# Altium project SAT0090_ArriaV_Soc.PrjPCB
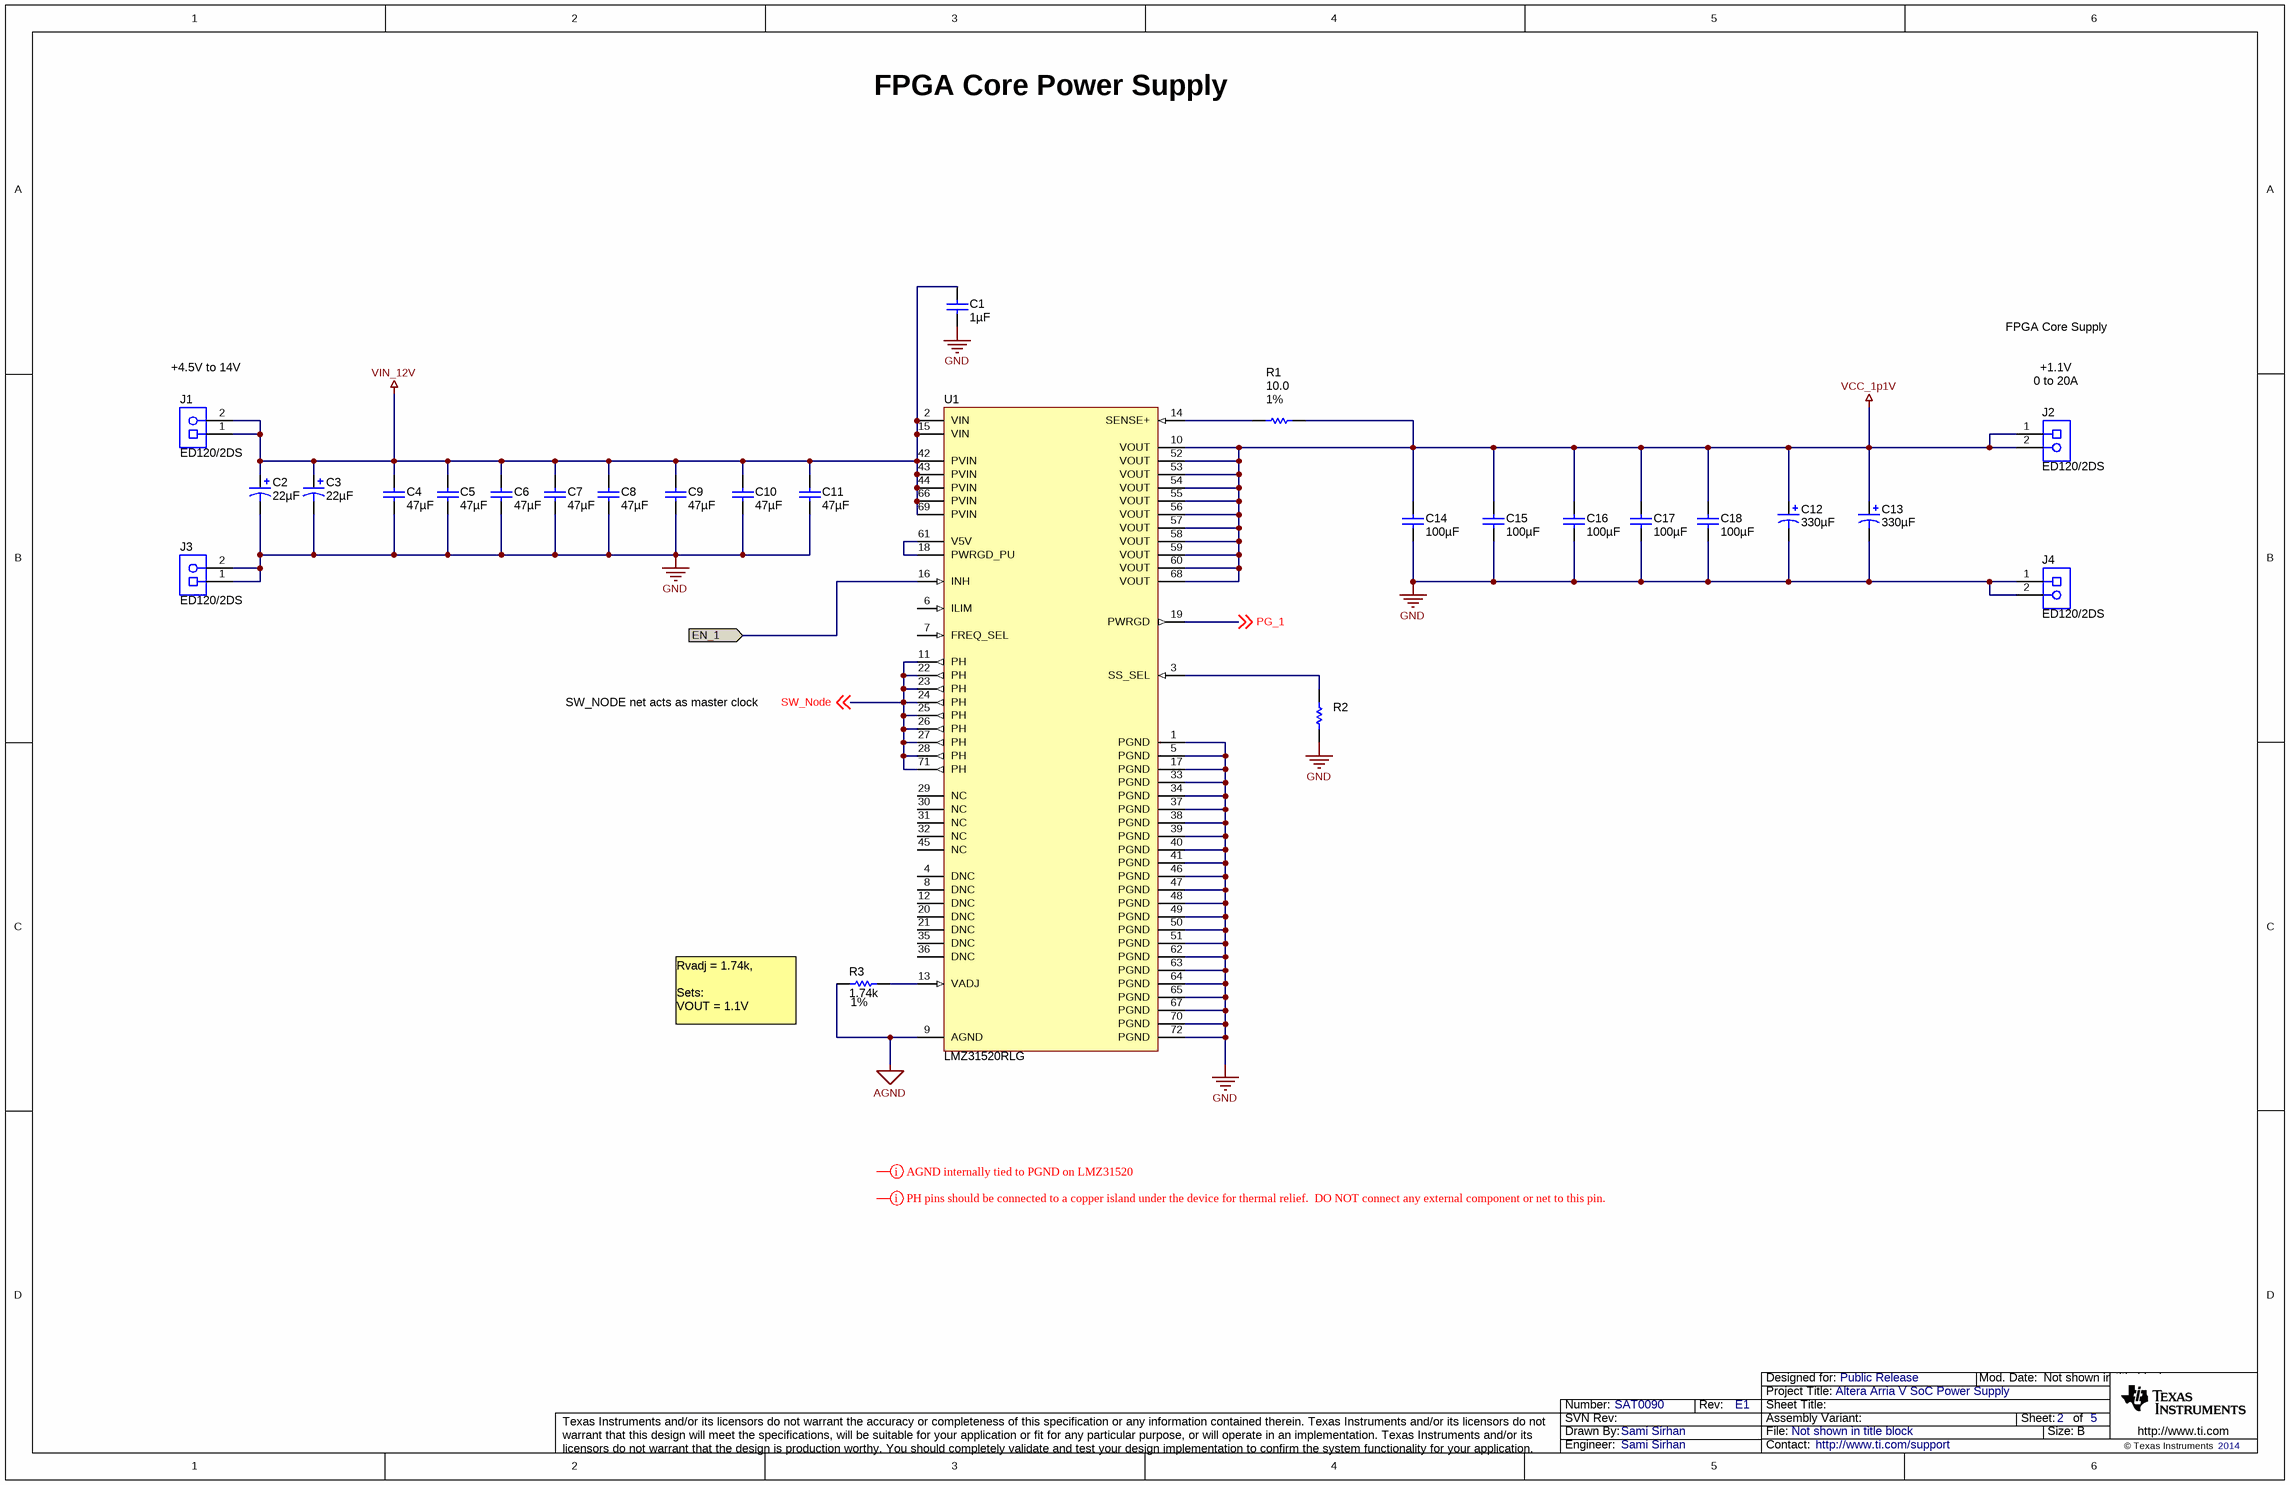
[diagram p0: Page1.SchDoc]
CopyrightYear: 2014; PCB_Layout: Sami Sirhan; PCB_Rev: E1; PRJ_Customer: Public Release; PRJ_Engineer: Sami Sirhan; PRJ_Number: SAT0090; PRJ_Title: Altera Arria V SoC Power Supply; SCH_Rev: E1; TechSupport: http://www.ti.com/support
5 sheets, 142 parts. Net scope: flat (ports and power ports of the same name join across sheets).
Sheets:
  Page1.SchDoc
  Page2.SchDoc
  Page3.SchDoc
  Page4.SchDoc
  Cover Sheet_ANSI-B.SchDoc

## Sheet Page1.SchDoc
size 431 x 279 mm; Date: Not shown in title block; ApprovedBy: Not shown in title block; CheckedBy: Not shown in title block; Author: Not shown in title block; CompanyName: Not shown in title block; DrawnBy: Sami Sirhan; Engineer: Not shown in title block; Organization: Not shown in title block; Address1: Not shown in title block; Address2: Not shown in title block; Address3: Not shown in title block; Address4: Not shown in title block; DocumentNumber: 2; Revision: Use project parameter SCH_Rev; SheetNumber: 2; SheetTotal: 5; PageSetup: Record=PageOptions|CenterHorizontal=True|CenterVertical=True|PrintScale=1.00|XCorrection=1.00|YCorrection=1.00|PrintKind=0|BorderSize=5000000|LeftOffset=0|BottomOffset=0|Orientation=2|PaperLength=1000|PaperWidth=1000|Scale=100|PaperSource=15|PrintQuality=600|MediaType=1|DitherType=10|PaperKind=Letter|PrintScaleMode=1

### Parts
(Parts that share a designator on the sheet are numbered #1, #2 ... from top to bottom, then left to right.)
C1#1  ValueDisplayed: 1µF  [0603]  (hidden comment: GRM188R61E105KA12D)
C2  ValueDisplayed: 22µF  [SM_RADIAL_C]  (hidden comment: EEE-FC1C220R)
C3  ValueDisplayed: 22µF  [SM_RADIAL_C]  (hidden comment: EEE-FC1C220R)
C4  ValueDisplayed: 47µF  [1210]  (hidden comment: GRM32ER61C476KE15L)
C5  ValueDisplayed: 47µF  [1210]  (hidden comment: GRM32ER61C476KE15L)
C6  ValueDisplayed: 47µF  [1210]  (hidden comment: GRM32ER61C476KE15L)
C7  ValueDisplayed: 47µF  [1210]  (hidden comment: GRM32ER61C476KE15L)
C8  ValueDisplayed: 47µF  [1210]  (hidden comment: GRM32ER61C476KE15L)
C9  ValueDisplayed: 47µF  [1210]  (hidden comment: GRM32ER61C476KE15L)
C10  ValueDisplayed: 47µF  [1210]  (hidden comment: GRM32ER61C476KE15L)
C11  ValueDisplayed: 47µF  [1210]  (hidden comment: GRM32ER61C476KE15L)
C12  ValueDisplayed: 330µF  [CAPAE_SP-Cap_Standard]  (hidden comment: EEF-SX0D331XE)
C13  ValueDisplayed: 330µF  [CAPAE_SP-Cap_Standard]  (hidden comment: EEF-SX0D331XE)
C14  ValueDisplayed: 100µF  [1210]  (hidden comment: GRM32ER60J107ME20L)
C15  ValueDisplayed: 100µF  [1210]  (hidden comment: GRM32ER60J107ME20L)
C16  ValueDisplayed: 100µF  [1210]  (hidden comment: GRM32ER60J107ME20L)
C17  ValueDisplayed: 100µF  [1210]  (hidden comment: GRM32ER60J107ME20L)
C18  ValueDisplayed: 100µF  [1210]  (hidden comment: GRM32ER60J107ME20L)
J1  ED120/2DS  [CONN_ED120-2DS]
J2  ED120/2DS  [CONN_ED120-2DS]
J3  ED120/2DS  [CONN_ED120-2DS]
J4  ED120/2DS  [CONN_ED120-2DS]
R1  value 10.0  Value1: 1%  [0603]  (hidden comment: CRCW060310R0FKEA)
R2  CRCW06030000Z0EA  [0603]  (value not drawn)
R3  value 1.74k  Value1: 1%  [0603]  (hidden comment: CRCW06031K74FKEA)
U1  LMZ31520RLG  [RLG0072A]

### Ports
EN_1 (in)

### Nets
AGND: R3.2 U1.9(AGND)
GND: C1#1.2 C2.2(-) C3.2(-) C4.2 C5.2 C6.2 C7.2 C8.2 C9.2 C10.2 C11.2 C12.2(-) C13.2(-) C14.2 C15.2 C16.2 C17.2 C18.2 J3.1 J3.2 J4.1 J4.2 R2.1 U1.1(PGND) U1.5(PGND) U1.17(PGND) U1.33(PGND) U1.34(PGND) U1.37(PGND) U1.38(PGND) U1.39(PGND) U1.40(PGND) U1.41(PGND) U1.46(PGND) U1.47(PGND) U1.48(PGND) U1.49(PGND) U1.50(PGND) U1.51(PGND) U1.62(PGND) U1.63(PGND) U1.64(PGND) U1.65(PGND) U1.67(PGND) U1.70(PGND) U1.72(PGND)
VCC_1p1V: C12.1(+) C13.1(+) C14.1 C15.1 C16.1 C17.1 C18.1 J2.1 J2.2 R1.2 U1.10(VOUT) U1.52(VOUT) U1.53(VOUT) U1.54(VOUT) U1.55(VOUT) U1.56(VOUT) U1.57(VOUT) U1.58(VOUT) U1.59(VOUT) U1.60(VOUT) U1.68(VOUT)
VIN_12V: C1#1.1 C2.1(+) C3.1(+) C4.1 C5.1 C6.1 C7.1 C8.1 C9.1 C10.1 C11.1 J1.1 J1.2 U1.2(VIN) U1.15(VIN) U1.42(PVIN) U1.43(PVIN) U1.44(PVIN) U1.66(PVIN) U1.69(PVIN)
EN_1: U1.16(INH) ; port EN_1
PG_1: U1.19(PWRGD) ; off-sheet PG_1
SW_Node: U1.11(PH) U1.22(PH) U1.23(PH) U1.24(PH) U1.25(PH) U1.26(PH) U1.27(PH) U1.28(PH) U1.71(PH) ; off-sheet SW_Node
NetR1_1: R1.1 U1.14(SENSE+)
NetR2_2: R2.2 U1.3(SS_SEL)
NetR3_1: R3.1 U1.13(VADJ)
NetU1_18: U1.18(PWRGD_PU) U1.61(V5V)

Not connected (* = marked no-connect by the designer): U1 4(DNC) 6(ILIM) 7(FREQ_SEL) 8(DNC) 12(DNC) 20(DNC) 21(DNC) 29(NC) 30(NC) 31(NC) 32(NC) 35(DNC) 36(DNC) 45(NC)

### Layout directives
rule Undefined: (no net found under the mark)

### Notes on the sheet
- FPGA Core Power Supply
- (near J1) +4.5V to 14V
- +1.1V
- FPGA Core Supply
- (near J2) 0 to 20A
- SW_NODE net acts as master clock
- Rvadj = 1.74k,
  Sets:
  VOUT = 1.1V

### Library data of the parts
C1#1 = GRM188R61E105KA12D: CAP, CERM, 1uF, 25V, +/-10%, X5R, 0603; Manufacturer: MuRata; Polarized: N; CompType: Capacitor; U/M: EA; Cap_F: 0.000001; Tolerance_%: 10; Value1: Unknown; VDC_V: 25; TaMin_C: -55; TaMax_C: 85
C2 C3 = EEE-FC1C220R: CAP, AL, 22uF, 16V, +/-20%, 1.8 ohm, SMD; Manufacturer: Panasonic; Polarized: Y; CompType: Capacitor; U/M: EA; Cap_F: 0.000022; Tolerance_%: 20; Value1: 1.8 ohm; VDC_V: 16; ESR_Ohm: 1.8; IRMS_A: 0.08; TaMin_C: -40; TaMax_C: 105; Cap_Case: C
C4-C11 = GRM32ER61C476KE15L: CAP, CERM, 47uF, 16V, +/-10%, X5R, 1210; Manufacturer: MuRata; Polarized: N; CompType: Capacitor; U/M: EA; Cap_F: 0.000047; Tolerance_%: 10; Value1: Unknown; VDC_V: 16; TaMin_C: -55; TaMax_C: 85
C12 C13 = EEF-SX0D331XE: CAP, TA, 330uF, 2V, +/-20%, 0.006 ohm, SMD; Manufacturer: Panasonic; Polarized: Y; CompType: Capacitor; U/M: EA; Cap_F: 0.00033; Tolerance_%: 20; VDC_V: 2; ESR_Ohm: 0.006; IRMS_A: 3.5; TaMin_C: -40; TaMax_C: 105; Cap_Case: D
C14-C18 = GRM32ER60J107ME20L: CAP, CERM, 100uF, 6.3V, +/-20%, X5R, 1210; Manufacturer: MuRata; Polarized: N; CompType: Capacitor; U/M: EA; Cap_F: 0.0001; Tolerance_%: 20; ESR_Ohm: 0.002; Value1: 0.002 ohm; VDC_V: 6.3; TaMin_C: -55; TaMax_C: 85
J1-J4 = ED120/2DS: TERMINAL BLOCK 5.08MM VERT 2POS, TH; Manufacturer: On-Shore Technology; SymbolCreator: a0412235; U/M: EA
R1 = CRCW060310R0FKEA: RES, 10.0 ohm, 1%, 0.1W, 0603; Manufacturer: Vishay-Dale; CompType: Resistor; Res_ohm: 10; Value_Code: 10R0; Tolerance_%: 1; Power_W: 0.1; VDC_V: 75; TempCo: 100 ppm/C; EIA_Code: E96; U/M: EA
R2 = CRCW06030000Z0EA: RES, 0 ohm, 5%, 0.1W, 0603; Manufacturer: Vishay-Dale; CompType: Resistor; Value: 0; Value_Code: 0000; Tolerance_%: 5; Power_W: 0.1; VDC_V: 75; TempCo: 200 ppm/C; EIA_Code: E24; U/M: EA
R3 = CRCW06031K74FKEA: RES, 1.74k ohm, 1%, 0.1W, 0603; Manufacturer: Vishay-Dale; CompType: Resistor; Res_ohm: 1740; Value_Code: 1k74; Tolerance_%: 1; Power_W: 0.1; VDC_V: 75; TempCo: 100 ppm/C; EIA_Code: E96; U/M: EA
U1 = LMZ31520RLG: 20A SIMPLE SWITCHER(R) Power Module with 3.0V-14.5V Input, RLG0072A; Alternate Manufacturer: None; Manufacturer: Texas Instruments; SymbolCreator: a0799628; CompType: IC; U/M: EA

## Sheet Page2.SchDoc
size 431 x 279 mm; Date: Not shown in title block; ApprovedBy: Not shown in title block; CheckedBy: Not shown in title block; Author: Not shown in title block; CompanyName: Not shown in title block; Engineer: Not shown in title block; Organization: Not shown in title block; Address1: Not shown in title block; Address2: Not shown in title block; Address3: Not shown in title block; Address4: Not shown in title block; DocumentNumber: 3; Revision: Use project parameter SCH_Rev; SheetNumber: 3; SheetTotal: 5; PageSetup: Record=PageOptions|CenterHorizontal=True|CenterVertical=True|PrintScale=1.00|XCorrection=1.00|YCorrection=1.00|PrintKind=0|BorderSize=5000000|LeftOffset=0|BottomOffset=0|Orientation=2|PaperLength=1000|PaperWidth=1000|Scale=100|PaperSource=15|PrintQuality=600|MediaType=1|DitherType=10|PaperKind=Letter|PrintScaleMode=1
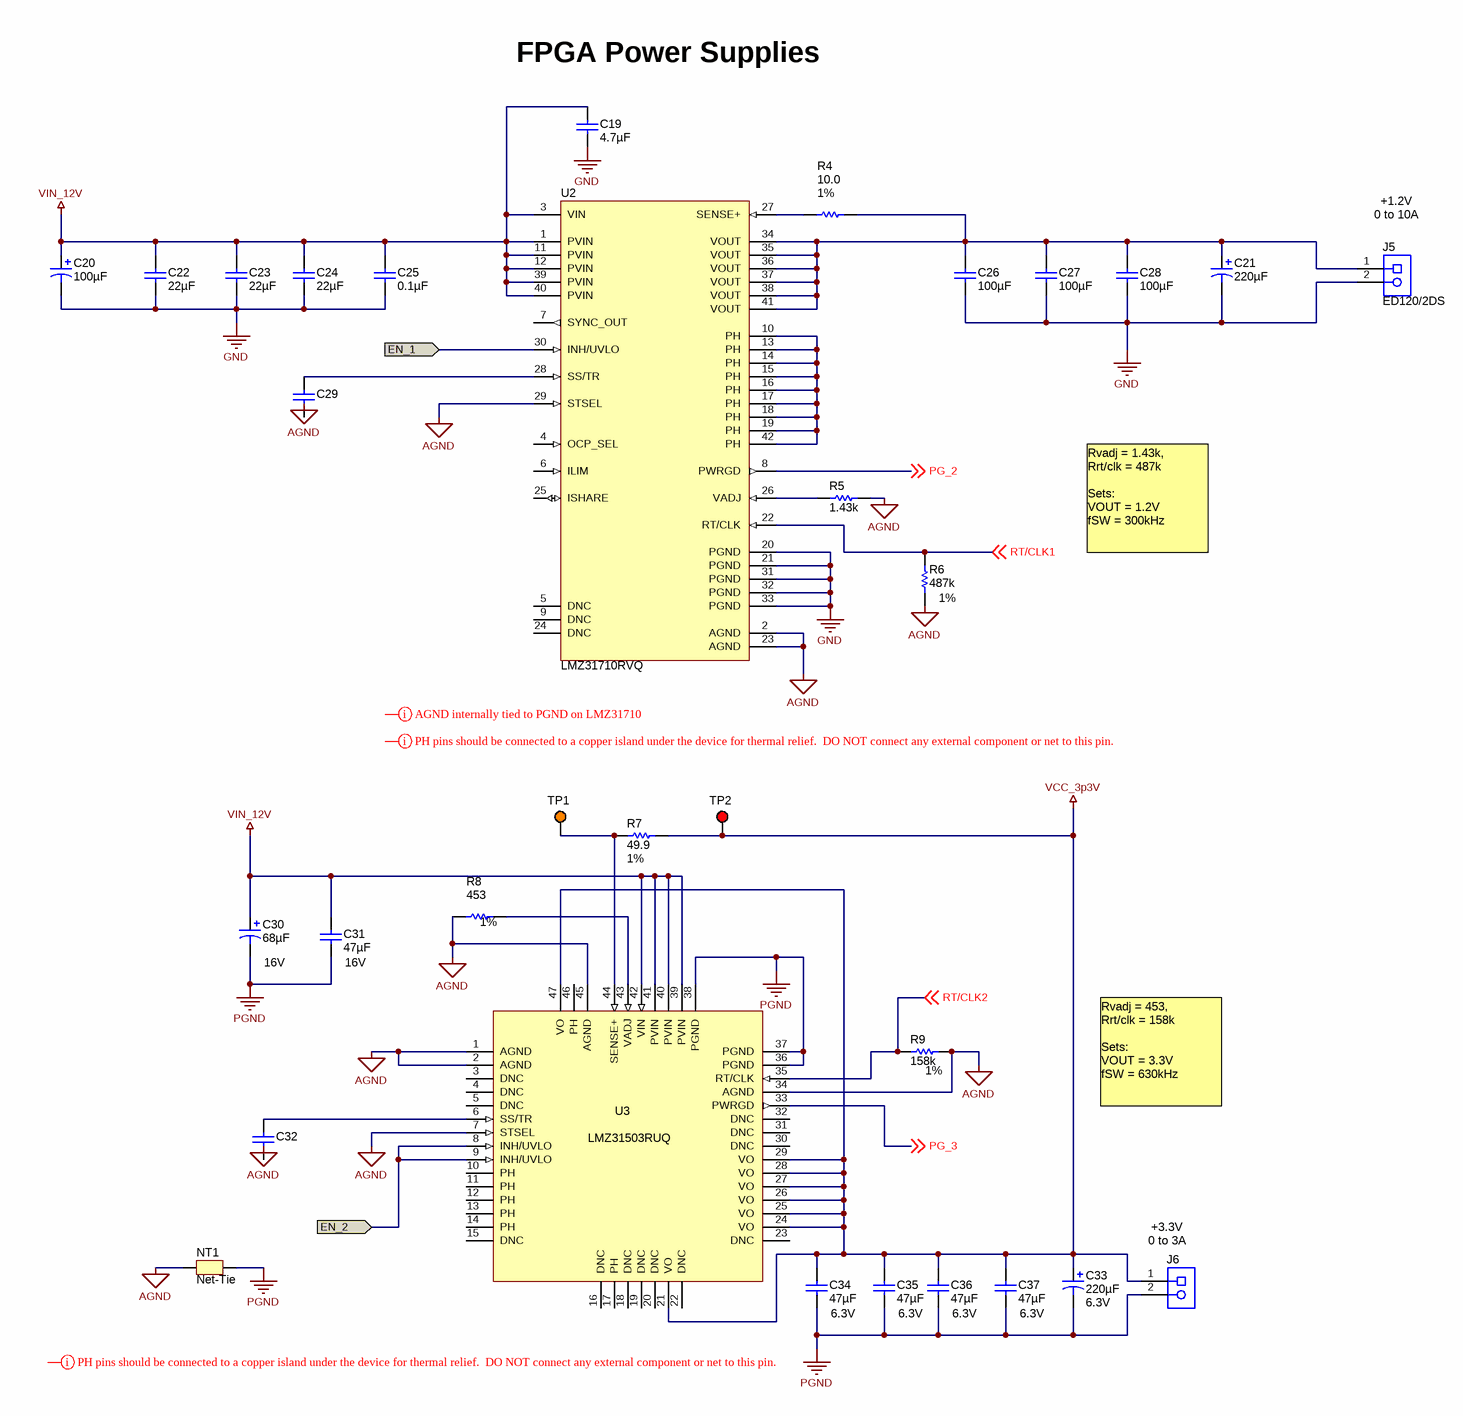
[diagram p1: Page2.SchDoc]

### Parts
C19  ValueDisplayed: 4.7µF  [1206]  (hidden comment: C3216X7R1E475K)
C20  ValueDisplayed: 100µF  [SM_RADIAL_6.3BMM]  (hidden comment: EEHZA1E101XP)
C21  ValueDisplayed: 220µF  [CAPSMT_6_UD]  (hidden comment: EEF-UD0E221LR)
C22  ValueDisplayed: 22µF  [1210]  (hidden comment: GRM32ER61E226KE15L)
C23  ValueDisplayed: 22µF  [1210]  (hidden comment: GRM32ER61E226KE15L)
C24  ValueDisplayed: 22µF  [1210]  (hidden comment: GRM32ER61E226KE15L)
C25  ValueDisplayed: 0.1µF  [0603]  (hidden comment: GRM188R61E104KA01D)
C26  ValueDisplayed: 100µF  [1210]  (hidden comment: GRM32ER60J107ME20L)
C27  ValueDisplayed: 100µF  [1210]  (hidden comment: GRM32ER60J107ME20L)
C28  ValueDisplayed: 100µF  [1210]  (hidden comment: GRM32ER60J107ME20L)
C29  GRM155R71H332KA01D  [0402]  (value not drawn)
C30  ValueDisplayed: 68µF  Value2: 16V  [TQC_D2]  (hidden comment: 16TQC68MYF)
C31  ValueDisplayed: 47µF  Value2: 16V  [1210]  (hidden comment: GRM32ER61C476ME15L)
C32  GRM155R71H332KA01D  [0402]  (value not drawn)
C33  ValueDisplayed: 220µF  Value2: 6.3V  [7343-31]  (hidden comment: T520D227M006ATE009)
C34  ValueDisplayed: 47µF  Value2: 6.3V  [1210]  (hidden comment: GRM32ER60J476ME20L)
C35  ValueDisplayed: 47µF  Value2: 6.3V  [1210]  (hidden comment: GRM32ER60J476ME20L)
C36  ValueDisplayed: 47µF  Value2: 6.3V  [1210]  (hidden comment: GRM32ER60J476ME20L)
C37  ValueDisplayed: 47µF  Value2: 6.3V  [1210]  (hidden comment: GRM32ER60J476ME20L)
J5  ED120/2DS  [CONN_ED120-2DS]
J6  ED120/2DS  [CONN_ED120-2DS]  (value not drawn)
NT1  Net-Tie  [Net-Tie_20milWide_60milLong]  (net tie, no BOM)
R4  value 10.0  Value1: 1%  [0603]  (hidden comment: CRCW060310R0FKEA)
R5  value 1.43k  [0603]  (hidden comment: RC0603FR-071K43L)
R6  value 487k  Value1: 1%  [0603]  (hidden comment: CRCW0603487KFKEA)
R7  value 49.9  Value1: 1%  [0603]  (hidden comment: CRCW060349R9FKEA)
R8  value 453  Value1: 1%  [0603]  (hidden comment: CRCW0603453RFKEA)
R9  value 158k  Value1: 1%  [0603]  (hidden comment: CRCW0603158KFKEA)
TP1  5013  [Keystone5013]  (value not drawn)
TP2  5010  [Keystone5010]  (value not drawn)
U2  LMZ31710RVQ  [RVQ0042A]
U3  LMZ31503RUQ  [RUQ0047A]

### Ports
EN_1 (in), EN_2 (in)

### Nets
AGND: NT1.1 R5.1 R6.1 R8.1 R9.1 U2.2(AGND) U2.23(AGND) U2.29(STSEL) U3.1(AGND) U3.2(AGND) U3.7(STSEL) U3.34(AGND) U3.45(AGND)
GND: C19.2 C20.2(-) C21.2(-) C22.2 C23.2 C24.2 C25.2 C26.2 C27.2 C28.2 J5.2 U2.20(PGND) U2.21(PGND) U2.31(PGND) U2.32(PGND) U2.33(PGND)
PGND: C30.2(-) C31.2 C33.2(-) C34.1 C35.1 C36.1 C37.1 J6.2 NT1.2 U3.36(PGND) U3.37(PGND) U3.38(PGND)
VCC_3p3V: C33.1(+) C34.2 C35.2 C36.2 C37.2 J6.1 R7.2 TP2.1 U3.21(VO) U3.24(VO) U3.25(VO) U3.26(VO) U3.27(VO) U3.28(VO) U3.29(VO) U3.47(VO)
VIN_12V: C19.1 C20.1(+) C22.1 C23.1 C24.1 C25.1 C30.1(+) C31.1 U2.1(PVIN) U2.3(VIN) U2.11(PVIN) U2.12(PVIN) U2.39(PVIN) U2.40(PVIN) U3.39(PVIN) U3.40(PVIN) U3.41(PVIN) U3.42(VIN)
EN_1: U2.30(INH/UVLO) ; port EN_1
EN_2: U3.8(INH/UVLO) U3.9(INH/UVLO) ; port EN_2
PG_2: U2.8(PWRGD) ; off-sheet PG_2
PG_3: U3.33(PWRGD) ; off-sheet PG_3
RT/CLK1: R6.2 U2.22(RT/CLK) ; off-sheet RT/CLK1
RT/CLK2: R9.2 U3.35(RT/CLK) ; off-sheet RT/CLK2
NetC21_1: C21.1(+) C26.1 C27.1 C28.1 J5.1 R4.2 U2.34(VOUT) U2.35(VOUT) U2.36(VOUT) U2.37(VOUT) U2.38(VOUT) U2.41(VOUT)
NetC29_1: C29.1 U2.28(SS/TR)
NetC32_1: C32.1 U3.6(SS/TR)
NetR4_1: R4.1 U2.27(SENSE+)
NetR5_2: R5.2 U2.26(VADJ)
NetR7_1: R7.1 TP1.1 U3.44(SENSE+)
NetR8_2: R8.2 U3.43(VADJ)
NetU2_10: U2.10(PH) U2.13(PH) U2.14(PH) U2.15(PH) U2.16(PH) U2.17(PH) U2.18(PH) U2.19(PH) U2.42(PH)

Not connected (* = marked no-connect by the designer): C29 2; C32 2; U2 4(OCP_SEL) 5(DNC) 6(ILIM) 7(SYNC_OUT) 9(DNC) 24(DNC) 25(ISHARE); U3 3(DNC) 4(DNC) 5(DNC) 10(PH) 11(PH) 12(PH) 13(PH) 14(PH) 15(DNC) 16(DNC) 17(PH) 18(DNC) 19(DNC) 20(DNC) 22(DNC) 23(DNC) 30(DNC) 31(DNC) 32(DNC) 46(PH)

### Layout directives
rule Undefined: (no net found under the mark)

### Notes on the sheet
- (near C19) FPGA Power Supplies
- +1.2V
- (near J5) 0 to 10A
- Rvadj = 1.43k,
  Rrt/clk = 487k
  Sets:
  VOUT = 1.2V
  fSW = 300kHz
- Rvadj = 453,
  Rrt/clk = 158k
  Sets:
  VOUT = 3.3V
  fSW = 630kHz
- (near J6) +3.3V
- (near J6) 0 to 3A
- Labels drawn without touching a wire or pin: AGND

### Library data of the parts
C19 = C3216X7R1E475K: CAP, CERM, 4.7uF, 25V, +/-10%, X7R, 1206; Manufacturer: TDK; Polarized: N; CompType: Capacitor; U/M: EA; Cap_F: 0.0000047; Tolerance_%: 10; ESR_Ohm: 0.0063; Value1: 0.0063 ohm; VDC_V: 25; TaMin_C: -55; TaMax_C: 125
C20 = EEHZA1E101XP: CAP, AL, 100uF, 25V, +/-20%, 30 ohm, SMD; Manufacturer: Panasonic; Polarized: Y; CompType: Capacitor; U/M: EA; Cap_F: 0.0001; Tolerance_%: 20; Value1: 30 ohm; VDC_V: 25; ESR_Ohm: 30; IRMS_A: 2; TaMin_C: -55; TaMax_C: 105
C21 = EEF-UD0E221LR: CAP, AL, 220uF, 2.5V, +/-20%, 0.009 ohm, SMD; Manufacturer: Panasonic; Polarized: Y; CompType: Capacitor; U/M: EA; Cap_F: 0.00022; Tolerance_%: 20; VDC_V: 2.5; ESR_Ohm: 0.009; IRMS_A: 3.4; TaMin_C: -40; TaMax_C: 105; Cap_Case: UD
C22-C24 = GRM32ER61E226KE15L: CAP, CERM, 22uF, 25V, +/-10%, X5R, 1210; Manufacturer: MuRata; Polarized: N; CompType: Capacitor; U/M: EA; Cap_F: 0.000022; Tolerance_%: 10; ESR_Ohm: 0.002; Value1: 0.002 ohm; VDC_V: 25; IRMS_A: 3.67; TaMin_C: -55; TaMax_C: 85
C25 = GRM188R61E104KA01D: CAP, CERM, 0.1uF, 25V, +/-10%, X5R, 0603; Manufacturer: MuRata; Polarized: N; CompType: Capacitor; U/M: EA; Cap_F: 0.0000001; Tolerance_%: 10; Value1: Unknown; VDC_V: 25; TaMin_C: -55; TaMax_C: 85
C26-C28 = GRM32ER60J107ME20L: as C14 on sheet Page1
C29 C32 = GRM155R71H332KA01D: CAP, CERM, 3300pF, 50V, +/-10%, X7R, 0402; Manufacturer: MuRata; Polarized: N; CompType: Capacitor; U/M: EA; Cap_F: 0.0000000033; Tolerance_%: 10; Value1: Unknown; VDC_V: 50; TaMin_C: -55; TaMax_C: 125
C30 = 16TQC68MYF: CAP, TA, 68uF, 16V, +/-20%, 0.05 ohm, SMD; Manufacturer: Panasonic; Polarized: Y; CompType: Capacitor; U/M: EA; Cap_F: 0.000068; Tolerance_%: 20; VDC_V: 16; ESR_Ohm: 0.05; IRMS_A: 1.5; TaMin_C: -55; TaMax_C: 105
C31 = GRM32ER61C476ME15L: CAP, CERM, 47uF, 16V, +/-20%, X5R, 1210; Manufacturer: MuRata; Polarized: N; CompType: Capacitor; U/M: EA; Cap_F: 0.000047; Tolerance_%: 20; ESR_Ohm: 0.002; Value1: 0.002 ohm; VDC_V: 16; TaMin_C: -55; TaMax_C: 85
C33 = T520D227M006ATE009: CAP, TA, 220uF, 6.3V, +/-20%, 0.009 ohm, SMD; Manufacturer: Kemet; Polarized: Y; CompType: Capacitor; U/M: EA; Cap_F: 0.00022; Tolerance_%: 20; VDC_V: 6.3; ESR_Ohm: 0.009; TaMin_C: -55; TaMax_C: 105; Cap_Case: D
C34-C37 = GRM32ER60J476ME20L: CAP, CERM, 47uF, 6.3V, +/-20%, X5R, 1210; Manufacturer: MuRata; Polarized: N; CompType: Capacitor; U/M: EA; Cap_F: 0.000047; Tolerance_%: 20; ESR_Ohm: 0.003; Value1: 0.003 ohm; VDC_V: 6.3; TaMin_C: -55; TaMax_C: 85
J5 J6 = ED120/2DS: as J1 on sheet Page1
NT1 = Net-Tie: Single point connection between nets.; SymbolCreator: codlsc
R4 = CRCW060310R0FKEA: as R1 on sheet Page1
R5 = RC0603FR-071K43L: RES, 1.43k ohm, 1%, 0.1W, 0603; Manufacturer: Yageo America; CompType: Resistor; Res_ohm: 1430; Value_Code: 1k43; Tolerance_%: 1; Power_W: 0.1; VDC_V: 150; TempCo: 200 ppm/C; EIA_Code: E96; U/M: EA
R6 = CRCW0603487KFKEA: RES, 487k ohm, 1%, 0.1W, 0603; Manufacturer: Vishay-Dale; CompType: Resistor; Res_ohm: 487000; Tolerance_%: 1; Power_W: 0.1; VDC_V: 75; TempCo: 100 ppm/C; EIA_Code: E96; U/M: EA
R7 = CRCW060349R9FKEA: RES, 49.9 ohm, 1%, 0.1W, 0603; Manufacturer: Vishay-Dale; CompType: Resistor; Value_Code: 49R9; Tolerance_%: 1; Power_W: 0.1; VDC_V: 75; TempCo: 100 ppm/C; EIA_Code: E96; U/M: EA
R8 = CRCW0603453RFKEA: RES, 453 ohm, 1%, 0.1W, 0603; Manufacturer: Vishay-Dale; CompType: Resistor; Value_Code: 453R; Tolerance_%: 1; Power_W: 0.1; VDC_V: 75; TempCo: 100 ppm/C; EIA_Code: E96; U/M: EA
R9 = CRCW0603158KFKEA: RES, 158k ohm, 1%, 0.1W, 0603; Manufacturer: Vishay-Dale; CompType: Resistor; Res_ohm: 158000; Tolerance_%: 1; Power_W: 0.1; VDC_V: 75; TempCo: 100 ppm/C; EIA_Code: E96; U/M: EA
TP1 = 5013: Test Point, Multipurpose, Orange, TH; Manufacturer: Keystone; CompType: Test Point Loop; U/M: EA
TP2 = 5010: Test Point, Multipurpose, Red, TH; Manufacturer: Keystone; CompType: Test Point Loop; U/M: EA
U2 = LMZ31710RVQ: 10A SIMPLE SWITCHER Power Module with 2.95V-17V Input and Current Sharing in QFN Package, RVQ0042A; Alternate Manufacturer: None; Manufacturer: Texas Instruments; SymbolCreator: a0411947; CompType: IC; U/M: EA
U3 = LMZ31503RUQ: 3A SIMPLE SWITCHER Power Module with 4.5V-14.5V Input in QFN Package, RUQ0047A; Alternate Manufacturer: None; Manufacturer: Texas Instruments; SymbolCreator: a0411947; CompType: IC; U/M: EA

## Sheet Page3.SchDoc
size 431 x 279 mm; Date: Not shown in title block; ApprovedBy: Not shown in title block; CheckedBy: Not shown in title block; Author: Not shown in title block; CompanyName: Not shown in title block; Engineer: Not shown in title block; Organization: Not shown in title block; Address1: Not shown in title block; Address2: Not shown in title block; Address3: Not shown in title block; Address4: Not shown in title block; DocumentNumber: 4; Revision: Use project parameter SCH_Rev; SheetNumber: 4; SheetTotal: 5; PageSetup: Record=PageOptions|CenterHorizontal=True|CenterVertical=True|PrintScale=1.00|XCorrection=1.00|YCorrection=1.00|PrintKind=0|BorderSize=5000000|LeftOffset=0|BottomOffset=0|Orientation=2|PaperLength=1000|PaperWidth=1000|Scale=100|PaperSource=15|PrintQuality=600|MediaType=1|DitherType=10|PaperKind=Letter|PrintScaleMode=1
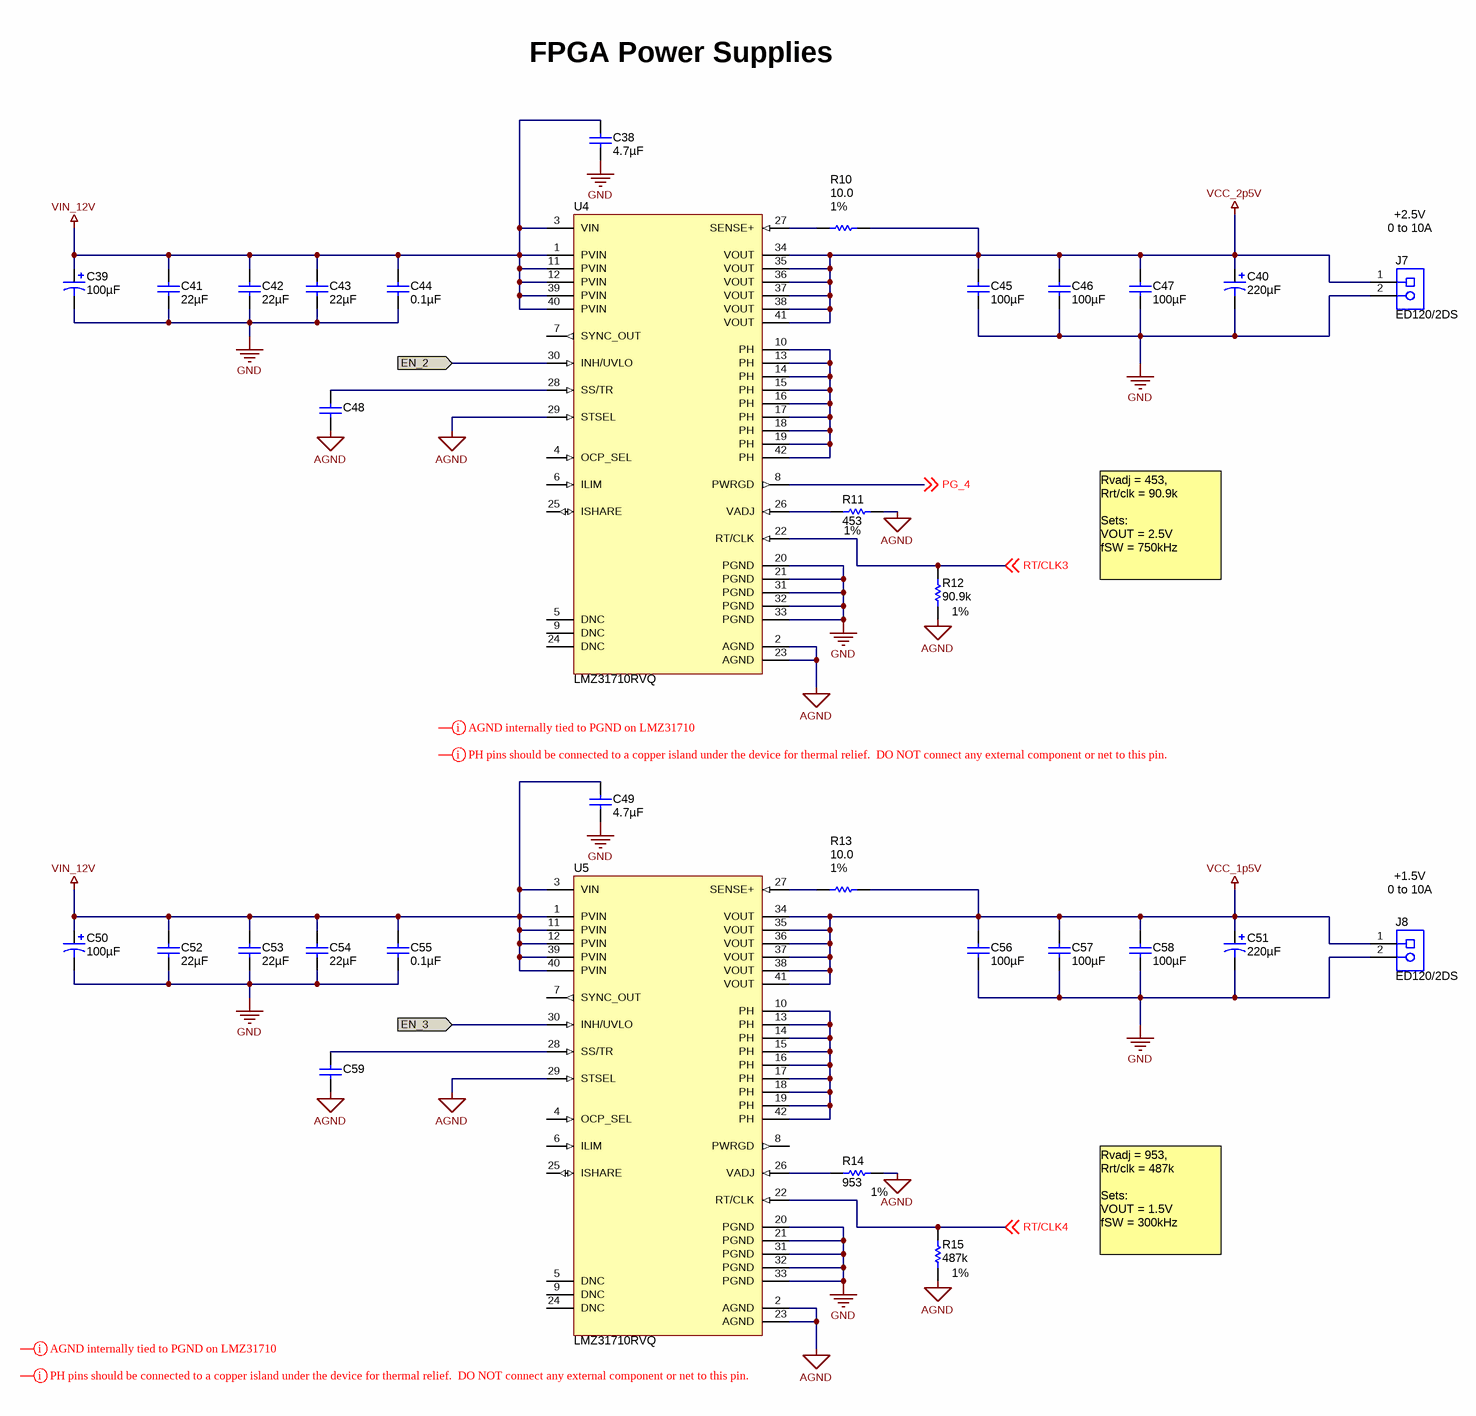
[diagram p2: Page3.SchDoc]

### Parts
C38  ValueDisplayed: 4.7µF  [1206]  (hidden comment: C3216X7R1E475K)
C39  ValueDisplayed: 100µF  [SM_RADIAL_6.3BMM]  (hidden comment: EEHZA1E101XP)
C40  ValueDisplayed: 220µF  [CAPSMT_6_UD]  (hidden comment: EEF-UD0E221LR)
C41  ValueDisplayed: 22µF  [1210]  (hidden comment: GRM32ER61E226KE15L)
C42  ValueDisplayed: 22µF  [1210]  (hidden comment: GRM32ER61E226KE15L)
C43  ValueDisplayed: 22µF  [1210]  (hidden comment: GRM32ER61E226KE15L)
C44  ValueDisplayed: 0.1µF  [0603]  (hidden comment: GRM188R61E104KA01D)
C45  ValueDisplayed: 100µF  [1210]  (hidden comment: GRM32ER60J107ME20L)
C46  ValueDisplayed: 100µF  [1210]  (hidden comment: GRM32ER60J107ME20L)
C47  ValueDisplayed: 100µF  [1210]  (hidden comment: GRM32ER60J107ME20L)
C48  GRM155R71H332KA01D  [0402]  (value not drawn)
C49  ValueDisplayed: 4.7µF  [1206]  (hidden comment: C3216X7R1E475K)
C50  ValueDisplayed: 100µF  [SM_RADIAL_6.3BMM]  (hidden comment: EEHZA1E101XP)
C51  ValueDisplayed: 220µF  [CAPSMT_6_UD]  (hidden comment: EEF-UD0E221LR)
C52  ValueDisplayed: 22µF  [1210]  (hidden comment: GRM32ER61E226KE15L)
C53  ValueDisplayed: 22µF  [1210]  (hidden comment: GRM32ER61E226KE15L)
C54  ValueDisplayed: 22µF  [1210]  (hidden comment: GRM32ER61E226KE15L)
C55  ValueDisplayed: 0.1µF  [0603]  (hidden comment: GRM188R61E104KA01D)
C56  ValueDisplayed: 100µF  [1210]  (hidden comment: GRM32ER60J107ME20L)
C57  ValueDisplayed: 100µF  [1210]  (hidden comment: GRM32ER60J107ME20L)
C58  ValueDisplayed: 100µF  [1210]  (hidden comment: GRM32ER60J107ME20L)
C59  GRM155R71H332KA01D  [0402]  (value not drawn)
J7  ED120/2DS  [CONN_ED120-2DS]
J8  ED120/2DS  [CONN_ED120-2DS]
R10  value 10.0  Value1: 1%  [0603]  (hidden comment: CRCW060310R0FKEA)
R11  value 453  Value1: 1%  [0603]  (hidden comment: CRCW0603453RFKEA)
R12  value 90.9k  Value1: 1%  [0603]  (hidden comment: CRCW060390K9FKEA)
R13  value 10.0  Value1: 1%  [0603]  (hidden comment: CRCW060310R0FKEA)
R14  value 953  Value1: 1%  [0603]  (hidden comment: CRCW0603953RFKEA)
R15  value 487k  Value1: 1%  [0603]  (hidden comment: RC0603FR-07487KL)
U4  LMZ31710RVQ  [RVQ0042A]
U5  LMZ31710RVQ  [RVQ0042A]

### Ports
EN_2 (in), EN_3 (in)

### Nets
AGND: C48.2 C59.2 R11.1 R12.1 R14.1 R15.1 U4.2(AGND) U4.23(AGND) U4.29(STSEL) U5.2(AGND) U5.23(AGND) U5.29(STSEL)
GND: C38.2 C39.2(-) C40.2(-) C41.2 C42.2 C43.2 C44.2 C45.2 C46.2 C47.2 C49.2 C50.2(-) C51.2(-) C52.2 C53.2 C54.2 C55.2 C56.2 C57.2 C58.2 J7.2 J8.2 U4.20(PGND) U4.21(PGND) U4.31(PGND) U4.32(PGND) U4.33(PGND) U5.20(PGND) U5.21(PGND) U5.31(PGND) U5.32(PGND) U5.33(PGND)
VCC_1p5V: C51.1(+) C56.1 C57.1 C58.1 J8.1 R13.2 U5.34(VOUT) U5.35(VOUT) U5.36(VOUT) U5.37(VOUT) U5.38(VOUT) U5.41(VOUT)
VCC_2p5V: C40.1(+) C45.1 C46.1 C47.1 J7.1 R10.2 U4.34(VOUT) U4.35(VOUT) U4.36(VOUT) U4.37(VOUT) U4.38(VOUT) U4.41(VOUT)
VIN_12V: C38.1 C39.1(+) C41.1 C42.1 C43.1 C44.1 C49.1 C50.1(+) C52.1 C53.1 C54.1 C55.1 U4.1(PVIN) U4.3(VIN) U4.11(PVIN) U4.12(PVIN) U4.39(PVIN) U4.40(PVIN) U5.1(PVIN) U5.3(VIN) U5.11(PVIN) U5.12(PVIN) U5.39(PVIN) U5.40(PVIN)
EN_2: U4.30(INH/UVLO) ; port EN_2
EN_3: U5.30(INH/UVLO) ; port EN_3
PG_4: U4.8(PWRGD) ; off-sheet PG_4
RT/CLK3: R12.2 U4.22(RT/CLK) ; off-sheet RT/CLK3
RT/CLK4: R15.2 U5.22(RT/CLK) ; off-sheet RT/CLK4
NetC48_1: C48.1 U4.28(SS/TR)
NetC59_1: C59.1 U5.28(SS/TR)
NetR10_1: R10.1 U4.27(SENSE+)
NetR11_2: R11.2 U4.26(VADJ)
NetR13_1: R13.1 U5.27(SENSE+)
NetR14_2: R14.2 U5.26(VADJ)
NetU4_10: U4.10(PH) U4.13(PH) U4.14(PH) U4.15(PH) U4.16(PH) U4.17(PH) U4.18(PH) U4.19(PH) U4.42(PH)
NetU5_10: U5.10(PH) U5.13(PH) U5.14(PH) U5.15(PH) U5.16(PH) U5.17(PH) U5.18(PH) U5.19(PH) U5.42(PH)

Not connected (* = marked no-connect by the designer): U4 4(OCP_SEL) 5(DNC) 6(ILIM) 7(SYNC_OUT) 9(DNC) 24(DNC) 25(ISHARE); U5 4(OCP_SEL) 5(DNC) 6(ILIM) 7(SYNC_OUT) 8(PWRGD) 9(DNC) 24(DNC) 25(ISHARE)

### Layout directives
rule Undefined: (no net found under the mark)

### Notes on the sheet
- FPGA Power Supplies
- +2.5V
- (near J7) 0 to 10A
- Rvadj = 453,
  Rrt/clk = 90.9k
  Sets:
  VOUT = 2.5V
  fSW = 750kHz
- +1.5V
- (near J8) 0 to 10A
- Rvadj = 953,
  Rrt/clk = 487k
  Sets:
  VOUT = 1.5V
  fSW = 300kHz

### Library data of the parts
C38 C49 = C3216X7R1E475K: as C19 on sheet Page2
C39 C50 = EEHZA1E101XP: as C20 on sheet Page2
C40 C51 = EEF-UD0E221LR: as C21 on sheet Page2
C41-C43 C52-C54 = GRM32ER61E226KE15L: as C22 on sheet Page2
C44 C55 = GRM188R61E104KA01D: as C25 on sheet Page2
C45-C47 C56-C58 = GRM32ER60J107ME20L: as C14 on sheet Page1
C48 C59 = GRM155R71H332KA01D: as C29 on sheet Page2
J7 J8 = ED120/2DS: as J1 on sheet Page1
R10 R13 = CRCW060310R0FKEA: as R1 on sheet Page1
R11 = CRCW0603453RFKEA: as R8 on sheet Page2
R12 = CRCW060390K9FKEA: RES, 90.9k ohm, 1%, 0.1W, 0603; Manufacturer: Vishay-Dale; CompType: Resistor; Res_ohm: 90900; Value_Code: 90k9; Tolerance_%: 1; Power_W: 0.1; VDC_V: 75; TempCo: 100 ppm/C; EIA_Code: E96; U/M: EA
R14 = CRCW0603953RFKEA: RES, 953 ohm, 1%, 0.1W, 0603; Manufacturer: Vishay-Dale; CompType: Resistor; Value_Code: 953R; Tolerance_%: 1; Power_W: 0.1; VDC_V: 75; TempCo: 100 ppm/C; EIA_Code: E96; U/M: EA
R15 = RC0603FR-07487KL: RES, 487k ohm, 1%, 0.1W, 0603; Manufacturer: Yageo America; CompType: Resistor; Res_ohm: 487000; Tolerance_%: 1; Power_W: 0.1; VDC_V: 150; TempCo: 200 ppm/C; EIA_Code: E96; U/M: EA
U4 U5 = LMZ31710RVQ: as U2 on sheet Page2

## Sheet Page4.SchDoc
size 431 x 279 mm; Date: Not shown in title block; ApprovedBy: Not shown in title block; CheckedBy: Not shown in title block; Author: Not shown in title block; CompanyName: Not shown in title block; Engineer: Not shown in title block; Organization: Not shown in title block; Address1: Not shown in title block; Address2: Not shown in title block; Address3: Not shown in title block; Address4: Not shown in title block; DocumentNumber: 5; Revision: Use project parameter SCH_Rev; SheetNumber: 5; SheetTotal: 5; PageSetup: Record=PageOptions|CenterHorizontal=True|CenterVertical=True|PrintScale=1.00|XCorrection=1.00|YCorrection=1.00|PrintKind=0|BorderSize=5000000|LeftOffset=0|BottomOffset=0|Orientation=2|PaperLength=1000|PaperWidth=1000|Scale=100|PaperSource=15|PrintQuality=600|MediaType=1|DitherType=10|PaperKind=Letter|PrintScaleMode=1
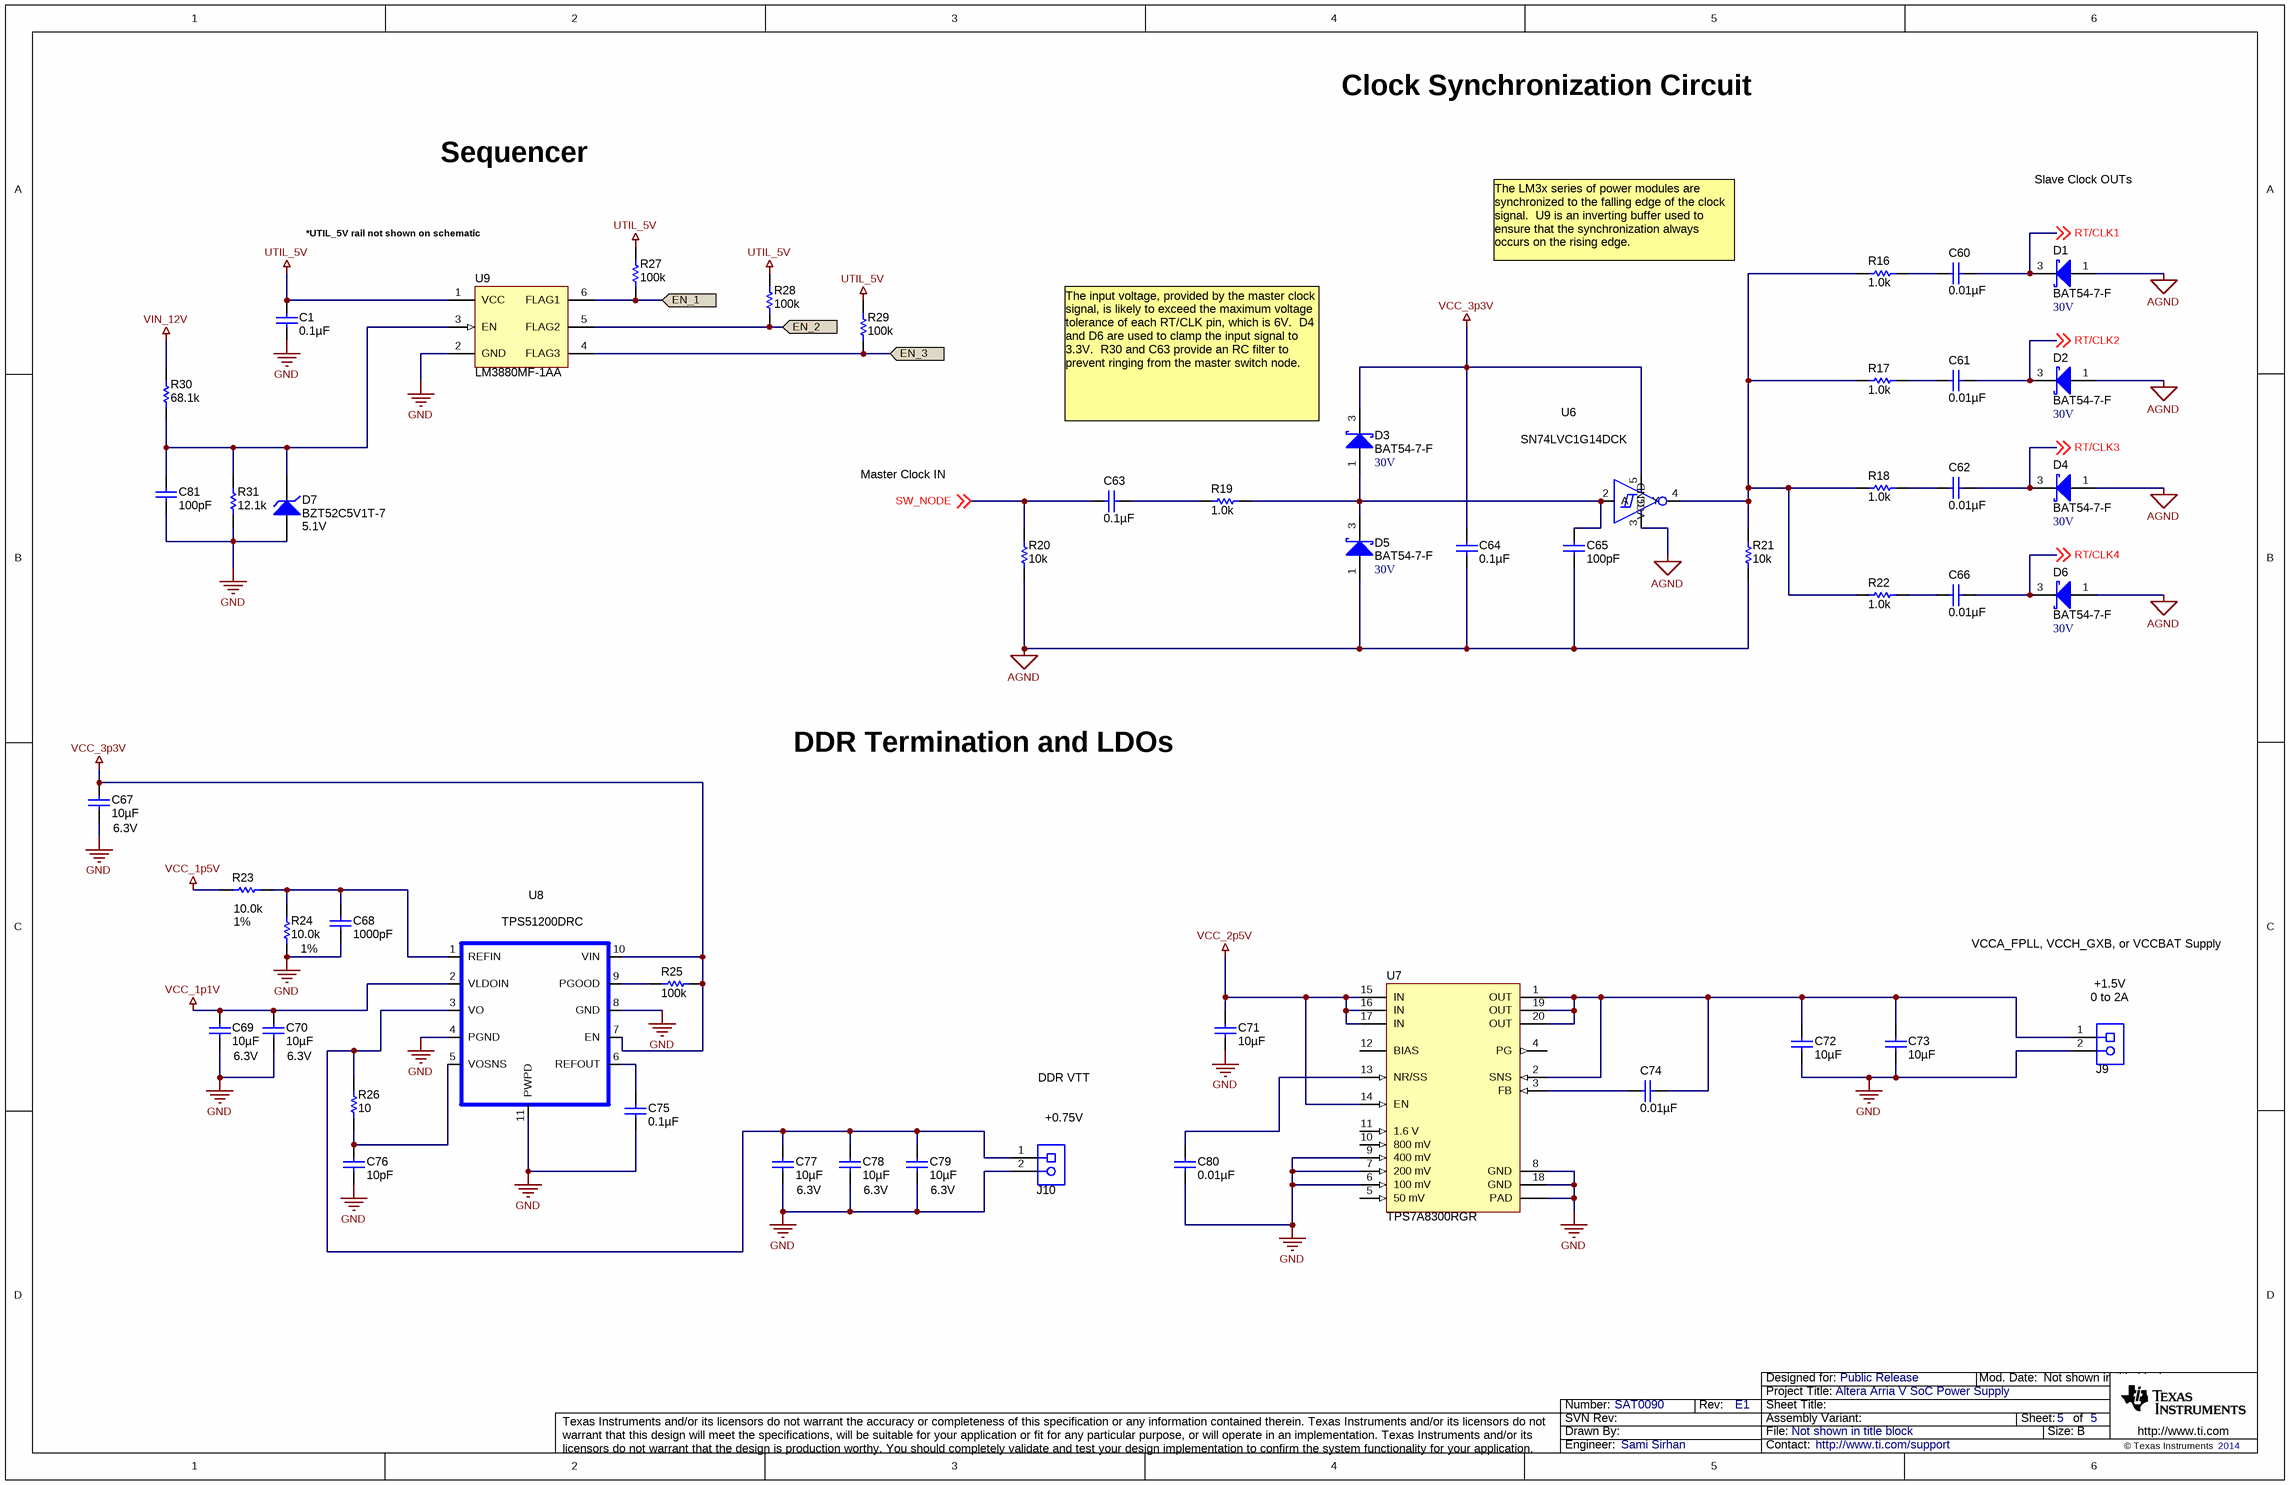
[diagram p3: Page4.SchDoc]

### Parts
(Parts that share a designator on the sheet are numbered #1, #2 ... from top to bottom, then left to right.)
C1#2  ValueDisplayed: 0.1µF  [0603]  (hidden comment: GRM188R61E104KA01D)
C60  ValueDisplayed: 0.01µF  [0603]  (hidden comment: C0603C103J5RACTU)
C61  ValueDisplayed: 0.01µF  [0603]  (hidden comment: C0603C103J5RACTU)
C62  ValueDisplayed: 0.01µF  [0603]  (hidden comment: C0603C103J5RACTU)
C63  ValueDisplayed: 0.1µF  [0603]  (hidden comment: GCM188R71H104KA57B)
C64  ValueDisplayed: 0.1µF  [0603]  (hidden comment: GCM188R71H104KA57B)
C65  ValueDisplayed: 100pF  [0603]  (hidden comment: 06035A101JAT2A)
C66  ValueDisplayed: 0.01µF  [0603]  (hidden comment: C0603C103J5RACTU)
C67  ValueDisplayed: 10µF  Value2: 6.3V  [0603]  (hidden comment: C0603C106M9PACTU)
C68  ValueDisplayed: 1000pF  [0603]  (hidden comment: 06031C102JAT2A)
C69  ValueDisplayed: 10µF  Value2: 6.3V  [0603]  (hidden comment: C0603C106M9PACTU)
C70  ValueDisplayed: 10µF  Value2: 6.3V  [0603]  (hidden comment: C0603C106M9PACTU)
C71  ValueDisplayed: 10µF  [0805_HV]  (hidden comment: GRM21BR61A106KE19L)
C72  ValueDisplayed: 10µF  [0805_HV]  (hidden comment: GRM21BR61A106KE19L)
C73  ValueDisplayed: 10µF  [0805_HV]  (hidden comment: GRM21BR61A106KE19L)
C74  ValueDisplayed: 0.01µF  [0603]  (hidden comment: C0603C103J5RACTU)
C75  ValueDisplayed: 0.1µF  [0603]  (hidden comment: GCM188R71H104KA57B)
C76  ValueDisplayed: 10pF  [0603]  (hidden comment: 06035A100JAT2A)
C77  ValueDisplayed: 10µF  Value2: 6.3V  [0603]  (hidden comment: C0603C106M9PACTU)
C78  ValueDisplayed: 10µF  Value2: 6.3V  [0603]  (hidden comment: C0603C106M9PACTU)
C79  ValueDisplayed: 10µF  Value2: 6.3V  [0603]  (hidden comment: C0603C106M9PACTU)
C80  ValueDisplayed: 0.01µF  [0603]  (hidden comment: C0603C103J5RACTU)
C81  ValueDisplayed: 100pF  [0603]  (hidden comment: GRM1885C2A101JA01D)
D1  BAT54-7-F  value 30V  [SOT-23]
D2  BAT54-7-F  value 30V  [SOT-23]
D3  BAT54-7-F  value 30V  [SOT-23]
D4  BAT54-7-F  value 30V  [SOT-23]
D5  BAT54-7-F  value 30V  [SOT-23]
D6  BAT54-7-F  value 30V  [SOT-23]
D7  BZT52C5V1T-7  value 5.1V  [SOD-523]
J9  ED120/2DS  [CONN_ED120-2DS]  (value not drawn)
J10  ED120/2DS  [CONN_ED120-2DS]  (value not drawn)
R16  value 1.0k  [0603]  (hidden comment: CRCW06031K00JNEA)
R17  value 1.0k  [0603]  (hidden comment: CRCW06031K00JNEA)
R18  value 1.0k  [0603]  (hidden comment: CRCW06031K00JNEA)
R19  value 1.0k  [0603]  (hidden comment: CRCW06031K00JNEA)
R20  value 10k  [0603]  (hidden comment: CRCW060310K0JNEA)
R21  value 10k  [0603]  (hidden comment: CRCW060310K0JNEA)
R22  value 1.0k  [0603]  (hidden comment: CRCW06031K00JNEA)
R23  value 10.0k  Value1: 1%  [0603]  (hidden comment: CRCW060310K0FKEA)
R24  value 10.0k  Value1: 1%  [0603]  (hidden comment: CRCW060310K0FKEA)
R25  value 100k  [0603]  (hidden comment: CRCW0603100KFKEA)
R26  value 10  [0603]  (hidden comment: CRCW060310R0JNEA)
R27  value 100k  [0603]  (hidden comment: CRCW0603100KJNEA)
R28  value 100k  [0603]  (hidden comment: CRCW0603100KJNEA)
R29  value 100k  [0603]  (hidden comment: CRCW0603100KJNEA)
R30  value 68.1k  [0603]  (hidden comment: CRCW060368K1FKEA)
R31  value 12.1k  [0603]  (hidden comment: CRCW060312K1FKEA)
U6  SN74LVC1G14DCK  [SOP_5P.65MM(DCK)]
U7  TPS7A8300RGR  [RGR0020A]
U8  TPS51200DRC  [DRC-10PA]
U9  LM3880MF-1AA  [MF06A_N]

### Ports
EN_1 (in), EN_2 (in), EN_3 (in)

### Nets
AGND: C64.1 C65.2 D1.1(A) D2.1(A) D4.1(A) D5.1(A) D6.1(A) R20.1 R21.1 U6.3(GND)
GND: C1#2.2 C67.1 C68.1 C69.1 C70.1 C71.2 C72.2 C73.2 C75.1 C76.1 C77.1 C78.1 C79.1 C80.1 C81.2 D7.2(A) J9.2 J10.2 R24.1 R31.1 U7.6(100_mV) U7.7(200_mV) U7.8(GND) U7.9(400_mV) U7.18(GND) U7.21(PAD) U8.4(PGND) U8.8(GND) U8.11(PWPD) U9.2(GND)
UTIL_5V: C1#2.1 R27.2 R28.2 R29.2 U9.1(VCC)
VCC_1p1V: C69.2 C70.2 U8.2(VLDOIN)
VCC_1p5V: R23.2
VCC_2p5V: C71.1 U7.14(EN) U7.15(IN) U7.16(IN) U7.17(IN)
VCC_3p3V: C64.2 C67.2 D3.3(K) R25.1 U6.5(VCC) U8.7(EN) U8.10(VIN)
VIN_12V: R30.2
EN_1: R27.1 U9.6(FLAG1) ; port EN_1
EN_2: R28.1 U9.5(FLAG2) ; port EN_2
EN_3: R29.1 U9.4(FLAG3) ; port EN_3
RT/CLK1: C60.2 D1.3(K) ; off-sheet RT/CLK1
RT/CLK2: C61.2 D2.3(K) ; off-sheet RT/CLK2
RT/CLK3: C62.2 D4.3(K) ; off-sheet RT/CLK3
RT/CLK4: C66.2 D6.3(K) ; off-sheet RT/CLK4
SW_Node: C63.1 R20.2 ; off-sheet SW_NODE
NetC60_1: C60.1 R16.1
NetC61_1: C61.1 R17.1
NetC62_1: C62.1 R18.1
NetC63_2: C63.2 R19.2
NetC65_1: C65.1 D3.1(A) D5.3(K) R19.1 U6.2(A)
NetC66_1: C66.1 R22.1
NetC68_2: C68.2 R23.1 R24.2 U8.1(REFIN)
NetC72_1: C72.1 C73.1 C74.2 J9.1 U7.1(OUT) U7.2(SNS) U7.19(OUT) U7.20(OUT)
NetC74_1: C74.1 U7.3(FB)
NetC75_2: C75.2 U8.6(REFOUT)
NetC76_2: C76.2 R26.1 U8.5(VOSNS)
NetC77_2: C77.2 C78.2 C79.2 J10.1 R26.2 U8.3(VO)
NetC80_2: C80.2 U7.13(NR/SS)
NetC81_1: C81.1 D7.1(K) R30.1 R31.2 U9.3(EN)
NetR16_2: R16.2 R17.2 R18.2 R21.2 R22.2 U6.4(Y)
NetR25_2: R25.2 U8.9(PGOOD)

Not connected (* = marked no-connect by the designer): U7 4(PG) 5(50_mV) 10(800_mV) 11(1.6_V) 12(BIAS)

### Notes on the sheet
- Clock Synchronization Circuit
- Sequencer
- *UTIL_5V rail not shown on schematic
- Slave Clock OUTs
- The LM3x series of power modules are synchronized to the falling edge of the clock signal.  U9 is an inverting buffer used to ensure that the synchronization always occurs on the rising edge.
- (near D3) The input voltage, provided by the master clock signal, is likely to exceed the maximum voltage tolerance of each RT/CLK pin, which is 6V.  D4 and D6 are used to clamp the input signal to 3.3V.  R30 and C63 provide an RC filter to prevent ringing from the master switch node.
- Master Clock IN
- DDR Termination and LDOs
- VCCA_FPLL, VCCH_GXB, or VCCBAT Supply
- (near J9) +1.5V
- (near J9) 0 to 2A
- DDR VTT
- (near J10) +0.75V

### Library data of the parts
C1#2 = GRM188R61E104KA01D: as C25 on sheet Page2
C60-C62 C66 C74 C80 = C0603C103J5RACTU: CAP, CERM, 0.01uF, 50V, +/-5%, X7R, 0603; Manufacturer: Kemet; Polarized: N; CompType: Capacitor; U/M: EA; Cap_F: 0.00000001; Tolerance_%: 5; Value1: Unknown; VDC_V: 50; TaMin_C: -55; TaMax_C: 125
C63 C64 C75 = GCM188R71H104KA57B: CAP, CERM, 0.1uF, 50V, +/-10%, X7R, 0603; Manufacturer: MuRata; Polarized: N; CompType: Capacitor; U/M: EA; Cap_F: 0.0000001; Tolerance_%: 10; ESR_Ohm: 0.02; Value1: 0.02 ohm; VDC_V: 50; IRMS_A: 1.84; TaMin_C: -55; TaMax_C: 125
C65 = 06035A101JAT2A: CAP, CERM, 100pF, 50V, +/-5%, C0G/NP0, 0603; Manufacturer: AVX; Polarized: N; CompType: Capacitor; U/M: EA; Cap_F: 0.0000000001; Tolerance_%: 5; ESR_Ohm: 0.119; Value1: 0.119 ohm; VDC_V: 50; TaMin_C: -55; TaMax_C: 125
C67 C69 C70 C77-C79 = C0603C106M9PACTU: CAP, CERM, 10uF, 6.3V, +/-20%, X5R, 0603; Manufacturer: Kemet; Polarized: N; CompType: Capacitor; U/M: EA; Cap_F: 0.00001; Tolerance_%: 20; ESR_Ohm: 0.004; Value1: 0.004 ohm; VDC_V: 6.3; IRMS_A: 8.9; TaMin_C: -55; TaMax_C: 85
C68 = 06031C102JAT2A: CAP, CERM, 1000pF, 100V, +/-5%, X7R, 0603; Manufacturer: AVX; Polarized: N; CompType: Capacitor; U/M: EA; Cap_F: 0.000000001; Tolerance_%: 5; ESR_Ohm: 0.276; Value1: 0.276 ohm; VDC_V: 100; TaMin_C: -55; TaMax_C: 125
C71-C73 = GRM21BR61A106KE19L: CAP, CERM, 10uF, 10V, +/-10%, X5R, 0805; Manufacturer: MuRata; Polarized: N; CompType: Capacitor; U/M: EA; Cap_F: 0.00001; Tolerance_%: 10; ESR_Ohm: 0.002; Value1: 0.002 ohm; TaMin_C: -55; TaMax_C: 85; Cap_Case: 0805
C76 = 06035A100JAT2A: CAP, CERM, 10pF, 50V, +/-5%, C0G/NP0, 0603; Manufacturer: AVX; Polarized: N; CompType: Capacitor; U/M: EA; Cap_F: 0.00000000001; Tolerance_%: 5; ESR_Ohm: 0.403; Value1: 0.403 ohm; VDC_V: 50; TaMin_C: -55; TaMax_C: 125
C81 = GRM1885C2A101JA01D: CAP, CERM, 100pF, 100V, +/-5%, C0G/NP0, 0603; Manufacturer: MuRata; Polarized: N; CompType: Capacitor; U/M: EA; Cap_F: 0.0000000001; Tolerance_%: 5; Value1: Unknown; VDC_V: 100; TaMin_C: -55; TaMax_C: 125
D1-D6 = BAT54-7-F: Diode, Schottky, 30V, 0.2A, SOT-23; Manufacturer: Diodes Inc.; U/M: EA; Vf_V: 0.65; Value2: 0.65V; Io_A: 0.2; Vr_V: 30; TJmax_C: 125
D7 = BZT52C5V1T-7: Diode, Zener, 5.1V, 300mW, SOD-523; Manufacturer: Diodes Inc.; SymbolCreator: a0412235; U/M: EA; Power_W: 0.3; Vz_V: 5.1; Value1: 0.3W; RJA_CperW: 417
J9 J10 = ED120/2DS: as J1 on sheet Page1
R16-R19 R22 = CRCW06031K00JNEA: RES, 1.0k ohm, 5%, 0.1W, 0603; Manufacturer: Vishay-Dale; CompType: Resistor; Res_ohm: 1000; Value_Code: 1k00; Tolerance_%: 5; Power_W: 0.1; VDC_V: 75; TempCo: 200 ppm/C; EIA_Code: E24; U/M: EA
R20 R21 = CRCW060310K0JNEA: RES, 10k ohm, 5%, 0.1W, 0603; Manufacturer: Vishay-Dale; CompType: Resistor; Res_ohm: 10000; Value_Code: 10k0; Tolerance_%: 5; Power_W: 0.1; VDC_V: 75; TempCo: 200 ppm/C; EIA_Code: E24; U/M: EA
R23 R24 = CRCW060310K0FKEA: RES, 10.0k ohm, 1%, 0.1W, 0603; Manufacturer: Vishay-Dale; CompType: Resistor; Res_ohm: 10000; Value_Code: 10k0; Tolerance_%: 1; Power_W: 0.1; VDC_V: 75; TempCo: 100 ppm/C; EIA_Code: E96; U/M: EA
R25 = CRCW0603100KFKEA: RES, 100k ohm, 1%, 0.1W, 0603; Manufacturer: Vishay-Dale; CompType: Resistor; Res_ohm: 100000; Tolerance_%: 1; Power_W: 0.1; VDC_V: 75; TempCo: 100 ppm/C; EIA_Code: E96; U/M: EA
R26 = CRCW060310R0JNEA: RES, 10 ohm, 5%, 0.1W, 0603; Manufacturer: Vishay-Dale; CompType: Resistor; Value_Code: 10R0; Tolerance_%: 5; Power_W: 0.1; VDC_V: 75; TempCo: 200 ppm/C; EIA_Code: E24; U/M: EA
R27-R29 = CRCW0603100KJNEA: RES, 100k ohm, 5%, 0.1W, 0603; Manufacturer: Vishay-Dale; CompType: Resistor; Res_ohm: 100000; Tolerance_%: 5; Power_W: 0.1; VDC_V: 75; TempCo: 200 ppm/C; EIA_Code: E24; U/M: EA
R30 = CRCW060368K1FKEA: RES, 68.1k ohm, 1%, 0.1W, 0603; Manufacturer: Vishay-Dale; CompType: Resistor; Res_ohm: 68100; Value_Code: 68k1; Tolerance_%: 1; Power_W: 0.1; VDC_V: 75; TempCo: 100 ppm/C; EIA_Code: E96; U/M: EA
R31 = CRCW060312K1FKEA: RES, 12.1k ohm, 1%, 0.1W, 0603; Manufacturer: Vishay-Dale; CompType: Resistor; Res_ohm: 12100; Value_Code: 12k1; Tolerance_%: 1; Power_W: 0.1; VDC_V: 75; TempCo: 100 ppm/C; EIA_Code: E96; U/M: EA
U6 = SN74LVC1G14DCK: IC, Single Schmitt-Trigger Inverter; Manufacturer: TI; Alternate Manufacturer: None; Area: 19,500
U7 = TPS7A8300RGR: 2-A, 6-µVRMS, RF, LDO Voltage Regulator, RGR0020A; Alternate Manufacturer: None; Manufacturer: Texas Instruments; SymbolCreator: a0411947; CompType: IC; U/M: EA
U8 = TPS51200DRC: IC, Sink/Source DDR Termination Regulator; Manufacturer: TI; Alternate Manufacturer: None; Area: 30400
U9 = LM3880MF-1AA: Power Sequencer, 6-pin SOT-23; Manufacturer: National Semiconductor; PackageTopMarking: F20A*XTT; PowerWise: N; CompType: MiscPower

## Sheet Cover Sheet_ANSI-B.SchDoc
size 431 x 279 mm; Date: Not shown in title block; ApprovedBy: Not shown in title block; CheckedBy: Not shown in title block; Author: Not shown in title block; CompanyName: Not shown in title block; Engineer: Not shown in title block; Organization: Not shown in title block; Address1: Not shown in title block; Address2: Not shown in title block; Address3: Not shown in title block; Address4: Not shown in title block; DocumentNumber: 1; Revision: Use project parameter SCH_Rev; SheetNumber: 1; SheetTotal: 5; PageSetup: Record=PageOptions|CenterHorizontal=True|CenterVertical=True|PrintScale=1.00|XCorrection=1.00|YCorrection=1.00|PrintKind=0|BorderSize=5000000|LeftOffset=0|BottomOffset=0|Orientation=2|PaperLength=1000|PaperWidth=1000|Scale=100|PaperSource=15|PrintQuality=600|MediaType=1|DitherType=10|PaperKind=Letter|PrintScaleMode=1
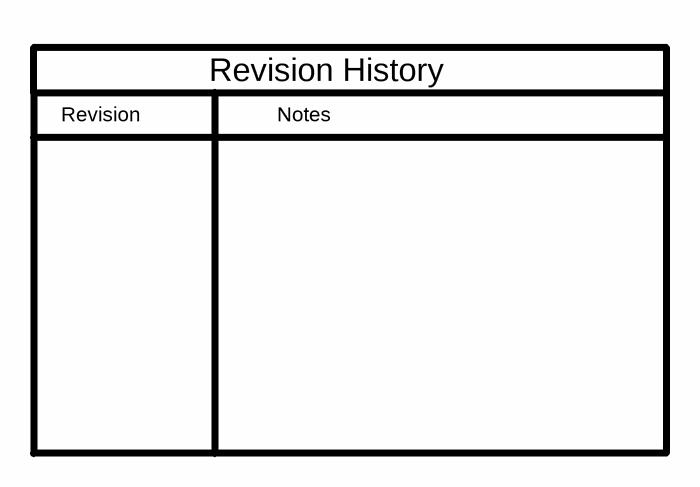
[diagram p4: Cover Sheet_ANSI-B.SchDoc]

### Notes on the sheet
- Revision
- Notes
- Revision History

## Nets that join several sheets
AGND: Page1 (R3.2 U1.9), Page2 (13 pins), Page3 (12 pins), Page4 (10 pins)
GND: Page1 (46 pins), Page2 (16 pins), Page3 (32 pins), Page4 (30 pins)
VCC_1p1V: Page1 (21 pins), Page4 (C69.2 C70.2 U8.2)
VCC_1p5V: Page3 (12 pins), Page4 (R23.2)
VCC_2p5V: Page3 (12 pins), Page4 (5 pins)
VCC_3p3V: Page2 (16 pins), Page4 (7 pins)
VIN_12V: Page1 (20 pins), Page2 (18 pins), Page3 (24 pins), Page4 (R30.2)
EN_1: Page1 (U1.16), Page2 (U2.30), Page4 (R27.1 U9.6)
EN_2: Page2 (U3.8 U3.9), Page3 (U4.30), Page4 (R28.1 U9.5)
EN_3: Page3 (U5.30), Page4 (R29.1 U9.4)
RT/CLK1: Page2 (R6.2 U2.22), Page4 (C60.2 D1.3)
RT/CLK2: Page2 (R9.2 U3.35), Page4 (C61.2 D2.3)
RT/CLK3: Page3 (R12.2 U4.22), Page4 (C62.2 D4.3)
RT/CLK4: Page3 (R15.2 U5.22), Page4 (C66.2 D6.3)
SW_Node: Page1 (9 pins), Page4 (C63.1 R20.2)

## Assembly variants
001: not fitted C29 C32 C48 C59 R2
